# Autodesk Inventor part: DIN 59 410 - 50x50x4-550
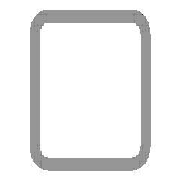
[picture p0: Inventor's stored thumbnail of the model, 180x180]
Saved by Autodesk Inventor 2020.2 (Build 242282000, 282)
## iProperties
Manager: www.cadconsulting.pl
Company: Fabian Stasiak CAD Consulting
Created: 2015-01
Part Number: DIN 59 410 - 50x50x4-550
Material: Stal, miękka
Description: Rurki stalowe o przekroju kwadratowym formowane na gorąco
Document SubType Name: Modellieren
Standard: DIN
Designer: F.Stasiak
Standards Organization: DIN
Language: pl-PL
Size Designation: 50x50x4
Categories: <MemberInstance><Categories><Category DisplayName="Kształtowniki konstrukcyjne" InternalName="089c4875-fa83-4c05-b084-43b9cc11f5ed" Mnemonic="GRDR"><CategoryPar
Stock Number: 50x50x4
Density: 7.85 g/cm^3
Appearance: Częściowo polerowana
Mass: 2999.78 g
Surface Area: 1924.59 cm^2
Volume: 382.138 cm^3
Catalog Web Link: www.expertbooks.pl
_CCFamilyMember: 40
_CCFamilyDisplayName: DIN 59410 (Kwadrat) - Rurki stalowe o przekroju kwadratowym formowane na gorąco
_FrameMemberDoc: Frame Member File
_Version: 15.0.0
_GetPNFromCC: 1
G_W: 50,000 mm
G_H: 50,000 mm
+46D8660F-3787-4C77-9D09-E9ED840BE6DD+CUTDETAIL1: Wytnij
+B27F17FC-E18D-433C-8E43-BE5209267DD6+CUTDETAIL2: Wytnij
G_L: 550,000 mm
IsCustomPart: 1
Author: F.Stasiak
Subject: Zbiór ćwiczeń. Autodesk Inventor 2020. Kurs Professional
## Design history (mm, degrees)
node "Płaszczyzna początkowa"
node "Płaszczyzna końcowa"
sketch "Szkic"
  geometry: L1 (-17, 25)-(17, 25); L2 (25, 17)-(25, -17); L3 (17, -25)-(-17, -25); L4 (-25, -17)-(-25, 17); L5 (-37.32, 0)-(37.32, 0) reference; L6 (0, -37.32)-(0, 37.32) reference; L7 (-17, 21)-(17, 21); L8 (21, 17)-(21, -17); L9 (17, -21)-(-17, -21); L10 (-21, -17)-(-21, 17); A1 r 8 centre (-17, 17) between (-17, 25) and (-25, 17); A2 r 8 centre (17, 17) between (25, 17) and (17, 25); A3 r 8 centre (17, -17) between (17, -25) and (25, -17); A4 r 8 centre (-17, -17) between (-25, -17) and (-17, -25); A5 r 4 centre (-17, 17) between (-17, 21) and (-21, 17); A6 r 4 centre (17, 17) between (21, 17) and (17, 21); A7 r 4 centre (17, -17) between (17, -21) and (21, -17); A8 r 4 centre (-17, -17) between (-21, -17) and (-17, -21); 3 further points
  constraints: 16 end point, 16 point on circle, 8 centre point, 8 tangent, 6 point on line, 4 parallel, 3 equal radius, 3 perpendicular, 1 horizontal, 7 other
  dimensions: "b" = 50 distance of point (-25, 25) point (25, 25); "msp_r" = 8 radius of A1 (= 2 x ParT); "d8" = 25 distance between parallel lines of L4 L6 (= d9); "d9" = 25 distance between parallel lines of L3 L5 (= 0.5 x b); "d10" = 4 distance between parallel lines of L3 L9 (= ParT)
extrude "Bryła" new body sketch "Szkic" taper "d4" = 0 deg; stored distance "NLG" = 10
node "Driven Length"
  sketch "Sketch2"
    geometry: L1 (0, 0)-(10, 0) reference
    constraints: 2 end point, 1 horizontal
  workplane "Work Plane3"
  sketch "Sketch3"
    geometry: L1 (-2, 25)-(12, 25) reference; L2 (-2, 575)-(12, 575) reference
    dimensions: "d14" = 550 distance between parallel lines of L1 L2 (derived)
node "Płaszczyzna konstrukcyjna4"
feature "Podział1"
node "Płaszczyzna konstrukcyjna5"
feature "Podział2"
body "Solid1"
other parameters: "ParT" = 4, "G_OFFSET_START" = -25 [user parameter; used in 1 equation term], "G_OFFSET_END" = -25 [user parameter; used in 1 equation term], "d11" = 25 (= -G_OFFSET_START), "d12" = 575 (= G_OFFSET_END + B_L), "G_L" = 550 (= d14) [user parameter], "d13" = 90 deg
